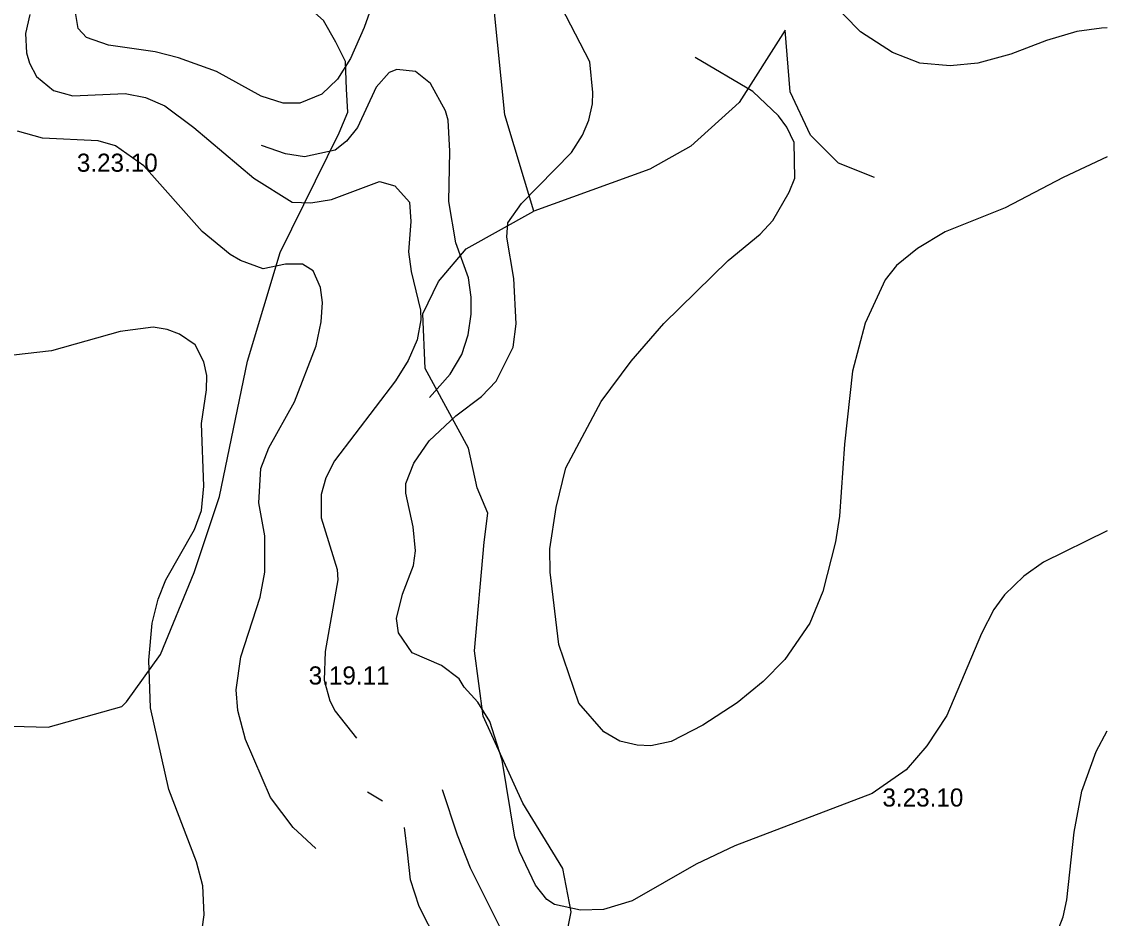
# Model space of a CAD drawing. Extents: x -662500 to -655523, y -1056000 to -1049993.
# Drawn here: x -659246.9 to -658797.7, y -1053965.2 to -1053594 of the extents above; entities that cross this region are included whole.
import ezdxf

# ---------------------------------------------------------------- set-up
doc = ezdxf.new("R2010")
doc.units = 0
doc.layers.add('Vrstva 24', color=7, linetype='Continuous')
doc.layers.add('Vrstva 7', color=7, linetype='Continuous')

msp = doc.modelspace()

# ---------------------------------------------------------------- linework, layer by layer
at = {"layer": 'Vrstva 24'}
for points in [[(-659035, -1053672.5), (-659047, -1053632.5), (-659051.5, -1053587.5), (-659048.5, -1053565), (-659028.5, -1053524.5), (-659027, -1053507.5), (-659035.5, -1053491), (-659047, -1053480.5), (-659063, -1053470.5), (-659081, -1053461.5), (-659140.5, -1053441.5), (-659164.5, -1053428), (-659179, -1053410), (-659188, -1053387.5), (-659191, -1053361.5)], [(-659256, -1053885.5), (-659236, -1053886), (-659205.5, -1053877.5), (-659203.5, -1053875.5), (-659189.5, -1053856), (-659175.5, -1053822), (-659165, -1053790.5), (-659153.5, -1053734.5), (-659140, -1053689.5), (-659115.5, -1053640), (-659112, -1053631.5), (-659112.5, -1053622), (-659113, -1053610.5), (-659117, -1053602.5), (-659122, -1053593.5), (-659130.5, -1053586), (-659147, -1053562.5), (-659164, -1053523), (-659175, -1053505), (-659187, -1053493.5), (-659197.5, -1053486.5), (-659220, -1053478.5), (-659240.5, -1053474.5), (-659306, -1053467.5)], [(-658931, -1053597.5), (-658950, -1053627.5), (-658970, -1053645.5), (-658987, -1053655), (-659035, -1053672.5)], [(-658894, -1053658.5), (-658909, -1053652.5), (-658920.5, -1053641), (-658929, -1053623), (-658931, -1053597.5)], [(-659029.99, -1054000), (-659025, -1053989.5), (-659019.5, -1053962.5), (-659023, -1053944.5), (-659039.5, -1053917.5), (-659056, -1053881.5), (-659059.5, -1053854.5), (-659055.5, -1053809.5), (-659054, -1053797.5), (-659058.5, -1053787), (-659062, -1053770.5), (-659080, -1053737.5), (-659081, -1053715), (-659074.5, -1053701.5), (-659063, -1053688), (-659035, -1053672.5)]]:
    msp.add_lwpolyline(points, dxfattribs=at)
at = {"layer": 'Vrstva 7'}
for p, q in [((-659011.91, -1053610.67), (-659033.28, -1053569.01)), ((-658899.89, -1053598.23), (-658927.8, -1053569.61)), ((-659099.23, -1053579.3), (-659105.21, -1053596.38)), ((-659223.53, -1053596.81), (-659224.67, -1053590.25)), ((-659243.6, -1053590.97), (-659245.31, -1053598.94)), ((-659245.31, -1053598.94), (-659244.88, -1053606.92)), ((-659220.11, -1053600.51), (-659223.53, -1053596.81)), ((-659105.21, -1053596.38), (-659110.9, -1053609.2)), ((-658886.65, -1053606.77), (-658899.89, -1053598.23)), ((-658810.34, -1053598.09), (-658822.87, -1053601.79)), ((-658800.08, -1053596.67), (-658810.34, -1053598.09)), ((-658797.74, -1053596.59), (-658800.08, -1053596.67)), ((-659211, -1053603.78), (-659220.11, -1053600.51)), ((-659191.63, -1053606.49), (-659211, -1053603.78)), ((-658822.87, -1053601.79), (-658837.67, -1053607.49)), ((-659244.88, -1053606.92), (-659243.74, -1053611.19)), ((-659182.09, -1053608.91), (-659191.63, -1053606.49)), ((-658875.26, -1053611.19), (-658886.65, -1053606.77)), ((-658837.67, -1053607.49), (-658851.34, -1053611.19)), ((-659243.74, -1053611.19), (-659240.75, -1053616.74)), ((-659166.29, -1053614.61), (-659182.09, -1053608.91)), ((-659110.9, -1053609.2), (-659116.31, -1053617.74)), ((-659010.58, -1053623.28), (-659011.91, -1053610.67)), ((-658944.46, -1053622.86), (-658968.25, -1053608.76)), ((-658862.73, -1053612.33), (-658875.26, -1053611.19)), ((-658851.34, -1053611.19), (-658862.73, -1053612.33)), ((-659240.75, -1053616.74), (-659233.78, -1053622.44)), ((-659147.78, -1053624.86), (-659166.29, -1053614.61)), ((-659094.81, -1053615.03), (-659100.22, -1053621.16)), ((-659091.68, -1053613.75), (-659094.81, -1053615.03)), ((-659083.99, -1053614.61), (-659091.68, -1053613.75)), ((-659077.73, -1053619.59), (-659083.99, -1053614.61)), ((-659116.31, -1053617.74), (-659122.72, -1053624)), ((-659100.22, -1053621.16), (-659107.91, -1053637.81)), ((-659071.6, -1053630.84), (-659077.73, -1053619.59)), ((-659233.78, -1053622.44), (-659225.8, -1053624.72)), ((-659225.8, -1053624.72), (-659204.16, -1053623.72)), ((-659204.16, -1053623.72), (-659195.62, -1053625.43)), ((-659195.62, -1053625.43), (-659187.65, -1053628.84)), ((-659138.67, -1053627.71), (-659147.78, -1053624.86)), ((-659122.72, -1053624), (-659131.83, -1053627.71)), ((-659010.74, -1053628.02), (-659010.58, -1053623.28)), ((-658933.78, -1053632.97), (-658944.46, -1053622.86)), ((-659187.65, -1053628.84), (-659175.69, -1053637.81)), ((-659131.83, -1053627.71), (-659138.67, -1053627.71)), ((-659070.47, -1053634.82), (-659071.6, -1053630.84)), ((-659012.27, -1053634.76), (-659010.74, -1053628.02)), ((-659069.75, -1053647.64), (-659070.47, -1053634.82)), ((-659014.91, -1053640.94), (-659012.27, -1053634.76)), ((-658930.36, -1053637.67), (-658933.78, -1053632.97)), ((-659238.33, -1053642.23), (-659248.58, -1053639.38)), ((-659175.69, -1053637.81), (-659150.91, -1053658.74)), ((-659107.91, -1053637.81), (-659112.47, -1053643.51)), ((-658927.23, -1053644.08), (-658930.36, -1053637.67)), ((-659215.27, -1053643.37), (-659238.33, -1053642.23)), ((-659208.15, -1053645.36), (-659215.27, -1053643.37)), ((-659112.47, -1053643.51), (-659117.17, -1053647.21)), ((-659019.44, -1053648.22), (-659014.91, -1053640.94)), ((-658927.09, -1053658.74), (-658927.23, -1053644.08)), ((-659196.33, -1053653.62), (-659208.15, -1053645.36)), ((-659137.81, -1053648.64), (-659147.74, -1053645.23)), ((-659129.84, -1053649.92), (-659137.81, -1053648.64)), ((-659117.17, -1053647.21), (-659129.84, -1053649.92)), ((-659070.18, -1053668.43), (-659069.75, -1053647.64)), ((-659040.14, -1053669.28), (-659019.44, -1053648.22)), ((-658797.74, -1053650), (-658816.03, -1053658.46)), ((-659172.27, -1053680.81), (-659196.33, -1053653.62)), ((-659150.91, -1053658.74), (-659134.96, -1053668.71)), ((-659118.73, -1053667.57), (-659098.8, -1053660.17)), ((-659098.8, -1053660.17), (-659092.54, -1053662.02)), ((-659092.54, -1053662.02), (-659086.41, -1053668.71)), ((-658929.37, -1053664.58), (-658927.09, -1053658.74)), ((-658816.03, -1053658.46), (-658839.95, -1053670.99)), ((-658936.06, -1053676.26), (-658929.37, -1053664.58)), ((-659134.96, -1053668.71), (-659127.28, -1053669)), ((-659127.28, -1053669), (-659118.73, -1053667.57)), ((-659086.41, -1053668.71), (-659085.84, -1053676.68)), ((-659067.33, -1053685.51), (-659070.18, -1053668.43)), ((-659045.83, -1053677.25), (-659040.14, -1053669.28)), ((-658839.95, -1053670.99), (-658864.87, -1053680.96)), ((-659085.84, -1053676.68), (-659086.84, -1053689.21)), ((-659046.12, -1053683.23), (-659045.83, -1053677.25)), ((-658941.33, -1053681.95), (-658936.06, -1053676.26)), ((-659160.59, -1053690.35), (-659172.27, -1053680.81)), ((-659043.27, -1053700.32), (-659046.12, -1053683.23)), ((-658954.57, -1053692.92), (-658941.33, -1053681.95)), ((-658864.87, -1053680.96), (-658876.26, -1053687.93)), ((-659086.84, -1053689.21), (-659085.7, -1053697.47)), ((-659062.07, -1053700.03), (-659067.33, -1053685.51)), ((-658876.26, -1053687.93), (-658884.94, -1053694.91)), ((-659156.32, -1053692.92), (-659160.59, -1053690.35)), ((-659147.07, -1053696.33), (-659156.32, -1053692.92)), ((-658981.19, -1053718.97), (-658954.57, -1053692.92)), ((-659137.81, -1053694.34), (-659147.07, -1053696.33)), ((-659130.69, -1053694.34), (-659137.81, -1053694.34)), ((-659126.28, -1053697.19), (-659130.69, -1053694.34)), ((-659123.29, -1053704.02), (-659126.28, -1053697.19)), ((-659085.7, -1053697.47), (-659081.86, -1053713.42)), ((-658884.94, -1053694.91), (-658889.64, -1053700.89)), ((-659060.93, -1053708.01), (-659062.07, -1053700.03)), ((-659042.28, -1053719.11), (-659043.27, -1053700.32)), ((-658889.64, -1053700.89), (-658897.9, -1053718.83)), ((-659122.44, -1053710.29), (-659123.29, -1053704.02)), ((-659123, -1053718.26), (-659122.44, -1053710.29)), ((-659060.93, -1053715.13), (-659060.93, -1053708.01)), ((-659081.86, -1053713.42), (-659081.71, -1053717.41)), ((-659062.21, -1053723.67), (-659060.93, -1053715.13)), ((-659192.49, -1053720.4), (-659206.16, -1053722.25)), ((-659186.79, -1053721.39), (-659192.49, -1053720.4)), ((-659125.14, -1053728.23), (-659123, -1053718.26)), ((-659081.71, -1053717.41), (-659083.28, -1053725.66)), ((-659043.56, -1053728.8), (-659042.28, -1053719.11)), ((-658994.72, -1053734.49), (-658981.19, -1053718.97)), ((-658897.9, -1053718.83), (-658903.17, -1053738.62)), ((-659206.16, -1053722.25), (-659234.63, -1053730.22)), ((-659181.67, -1053723.39), (-659186.79, -1053721.39)), ((-659175.12, -1053727.8), (-659181.67, -1053723.39)), ((-659064.77, -1053731.78), (-659062.21, -1053723.67)), ((-659171.56, -1053734.78), (-659175.12, -1053727.8)), ((-659133.97, -1053751.43), (-659125.14, -1053728.23)), ((-659083.28, -1053725.66), (-659086.98, -1053734.21)), ((-659050.53, -1053742.75), (-659043.56, -1053728.8)), ((-659234.63, -1053730.22), (-659250.29, -1053732.07)), ((-659086.98, -1053734.21), (-659092.25, -1053742.61)), ((-659069.61, -1053739.9), (-659064.77, -1053731.78)), ((-659170.28, -1053740.47), (-659171.56, -1053734.78)), ((-659007.11, -1053751.29), (-658994.72, -1053734.49)), ((-658903.17, -1053738.62), (-658906.44, -1053768.95)), ((-659170.42, -1053746.45), (-659170.28, -1053740.47)), ((-659092.25, -1053742.61), (-659117.45, -1053775.78)), ((-659078.15, -1053749.58), (-659069.61, -1053739.9)), ((-659056.66, -1053749.16), (-659050.53, -1053742.75)), ((-659172.55, -1053760.4), (-659170.42, -1053746.45)), ((-659144.65, -1053770.37), (-659133.97, -1053751.43)), ((-659067.33, -1053757.13), (-659056.66, -1053749.16)), ((-659021.77, -1053778.63), (-659007.11, -1053751.29)), ((-659171.56, -1053786.32), (-659172.55, -1053760.4)), ((-659078.3, -1053767.52), (-659067.33, -1053757.13)), ((-659147.92, -1053778.91), (-659144.65, -1053770.37)), ((-659084.7, -1053776.78), (-659078.3, -1053767.52)), ((-658906.44, -1053768.95), (-658908.58, -1053798.7)), ((-659148.78, -1053793.15), (-659147.92, -1053778.91)), ((-659117.45, -1053775.78), (-659121.01, -1053782.76)), ((-659087.98, -1053785.18), (-659084.7, -1053776.78)), ((-659025.76, -1053795.15), (-659021.77, -1053778.63)), ((-659121.01, -1053782.76), (-659123.01, -1053789.74)), ((-659172.55, -1053796.28), (-659171.56, -1053786.32)), ((-659087.98, -1053789.17), (-659087.98, -1053785.18)), ((-659123.01, -1053789.74), (-659123.01, -1053799.42)), ((-659084.99, -1053803.12), (-659087.98, -1053789.17)), ((-659175.4, -1053804.26), (-659172.55, -1053796.28)), ((-659146.35, -1053806.82), (-659148.78, -1053793.15)), ((-659028.46, -1053812.23), (-659025.76, -1053795.15)), ((-659123.01, -1053799.42), (-659116.45, -1053820.77)), ((-658908.58, -1053798.7), (-658910.15, -1053809.38)), ((-659187.22, -1053825.04), (-659175.4, -1053804.26)), ((-659083.99, -1053813.08), (-659084.99, -1053803.12)), ((-658797.74, -1053804.79), (-658824.15, -1053817.78)), ((-659146.35, -1053821.91), (-659146.35, -1053806.82)), ((-658910.15, -1053809.38), (-658915.41, -1053829.89)), ((-659084.85, -1053819.06), (-659083.99, -1053813.08)), ((-659028.32, -1053821.91), (-659028.46, -1053812.23)), ((-659089.4, -1053831.02), (-659084.85, -1053819.06)), ((-658824.15, -1053817.78), (-658832.26, -1053823.48)), ((-659148.21, -1053832.16), (-659146.35, -1053821.91)), ((-659116.45, -1053820.77), (-659116.17, -1053825.04)), ((-659024.62, -1053851.81), (-659028.32, -1053821.91)), ((-658832.26, -1053823.48), (-658840.24, -1053831.31)), ((-659190.49, -1053833.02), (-659187.22, -1053825.04)), ((-659116.17, -1053825.04), (-659121.3, -1053854.66)), ((-659192.91, -1053842.99), (-659190.49, -1053833.02)), ((-659156.18, -1053856.94), (-659148.21, -1053832.16)), ((-659091.82, -1053840.99), (-659089.4, -1053831.02)), ((-658915.41, -1053829.89), (-658920.82, -1053842.99)), ((-658840.24, -1053831.31), (-658844.65, -1053837.29)), ((-658844.65, -1053837.29), (-658849.78, -1053847.26)), ((-659090.97, -1053846.97), (-659091.82, -1053840.99)), ((-659194.34, -1053858.36), (-659192.91, -1053842.99)), ((-658920.82, -1053842.99), (-658931.22, -1053858.08)), ((-659085.38, -1053855.31), (-659090.97, -1053846.97)), ((-658849.78, -1053847.26), (-658864.16, -1053881.14)), ((-659121.3, -1053854.66), (-659121.72, -1053866.62)), ((-659073.28, -1053860.57), (-659085.38, -1053855.31)), ((-659016.36, -1053876.07), (-659024.62, -1053851.81)), ((-659193.62, -1053878.01), (-659194.34, -1053858.36)), ((-659158.17, -1053870.61), (-659156.18, -1053856.94)), ((-658931.22, -1053858.08), (-658940.19, -1053867.19)), ((-659065.91, -1053865.96), (-659073.28, -1053860.57)), ((-659121.72, -1053866.62), (-659119.45, -1053875.16)), ((-659063.77, -1053869.47), (-659065.91, -1053865.96)), ((-658940.19, -1053867.19), (-658950.87, -1053876.02)), ((-659157.46, -1053879.15), (-659158.17, -1053870.61)), ((-659058.22, -1053875.73), (-659063.77, -1053869.47)), ((-659186.08, -1053911.9), (-659193.62, -1053878.01)), ((-659119.45, -1053875.16), (-659117.17, -1053879.43)), ((-659053.24, -1053883.71), (-659058.22, -1053875.73)), ((-659006.11, -1053887.98), (-659016.36, -1053876.07)), ((-658950.87, -1053876.02), (-658965.1, -1053885.27)), ((-659154.33, -1053891.11), (-659157.46, -1053879.15)), ((-659117.17, -1053879.43), (-659108.34, -1053890.52)), ((-658864.16, -1053881.14), (-658872.41, -1053893.81)), ((-659048.11, -1053899.65), (-659053.24, -1053883.71)), ((-658965.1, -1053885.27), (-658978.2, -1053891.96)), ((-659143.94, -1053915.17), (-659154.33, -1053891.11)), ((-658999.42, -1053891.82), (-659006.11, -1053887.98)), ((-658802.36, -1053896.09), (-658797.74, -1053887.54)), ((-658992.3, -1053893.53), (-658999.42, -1053891.82)), ((-658986.6, -1053893.81), (-658992.3, -1053893.53)), ((-658978.2, -1053891.96), (-658986.6, -1053893.81)), ((-658872.41, -1053893.81), (-658880.96, -1053903.64)), ((-658808.34, -1053912.47), (-658802.36, -1053896.09)), ((-659042.84, -1053931.55), (-659048.11, -1053899.65)), ((-658880.96, -1053903.64), (-658895.05, -1053913.46)), ((-659174.55, -1053941.8), (-659186.08, -1053911.9)), ((-659103.81, -1053912.87), (-659097.59, -1053916.54)), ((-659066.62, -1053930.69), (-659072.74, -1053912.04)), ((-658895.05, -1053913.46), (-658951.86, -1053935.1)), ((-658811.47, -1053929.55), (-658808.34, -1053912.47)), ((-659134.54, -1053927.56), (-659143.94, -1053915.17)), ((-659125.27, -1053936.29), (-659134.54, -1053927.56)), ((-659087.27, -1053937.81), (-659088.55, -1053927.56)), ((-659061.21, -1053944.36), (-659066.62, -1053930.69)), ((-659040.99, -1053937.53), (-659042.84, -1053931.55)), ((-658814.47, -1053957.46), (-658811.47, -1053929.55)), ((-658951.86, -1053935.1), (-658967.81, -1053942.79)), ((-659085.99, -1053949.2), (-659087.27, -1053937.81)), ((-659034.3, -1053951.48), (-659040.99, -1053937.53)), ((-659171.98, -1053951.76), (-659174.55, -1053941.8)), ((-659045.26, -1053976.25), (-659061.21, -1053944.36)), ((-658967.81, -1053942.79), (-658994.29, -1053957.89)), ((-659082.43, -1053960.31), (-659085.99, -1053949.2)), ((-659171.41, -1053963.72), (-659171.98, -1053951.76)), ((-659029.6, -1053957.32), (-659034.3, -1053951.48)), ((-659026.47, -1053959.45), (-659029.6, -1053957.32)), ((-658994.29, -1053957.89), (-659006.25, -1053961.45)), ((-658816.03, -1053964.58), (-658814.47, -1053957.46)), ((-659074.88, -1053975.11), (-659082.43, -1053960.31)), ((-659015.65, -1053961.73), (-659026.47, -1053959.45)), ((-659006.25, -1053961.45), (-659015.65, -1053961.73)), ((-659172.27, -1053969.7), (-659171.41, -1053963.72)), ((-658820.02, -1053974.83), (-658816.03, -1053964.58))]:
    msp.add_line(p, q, dxfattribs=at)

# ---------------------------------------------------------------- texts
at = {"layer": 'Vrstva 24'}
for s, p in [('3.23.10', (-659224.09, -1053656.13)), ('3.19.11', (-659128.16, -1053868.38)), ('3.23.10', (-658890.77, -1053918.9))]:
    msp.add_text(s, height=7.5, dxfattribs=at).set_placement(p)

doc.saveas('drawing.dxf')
